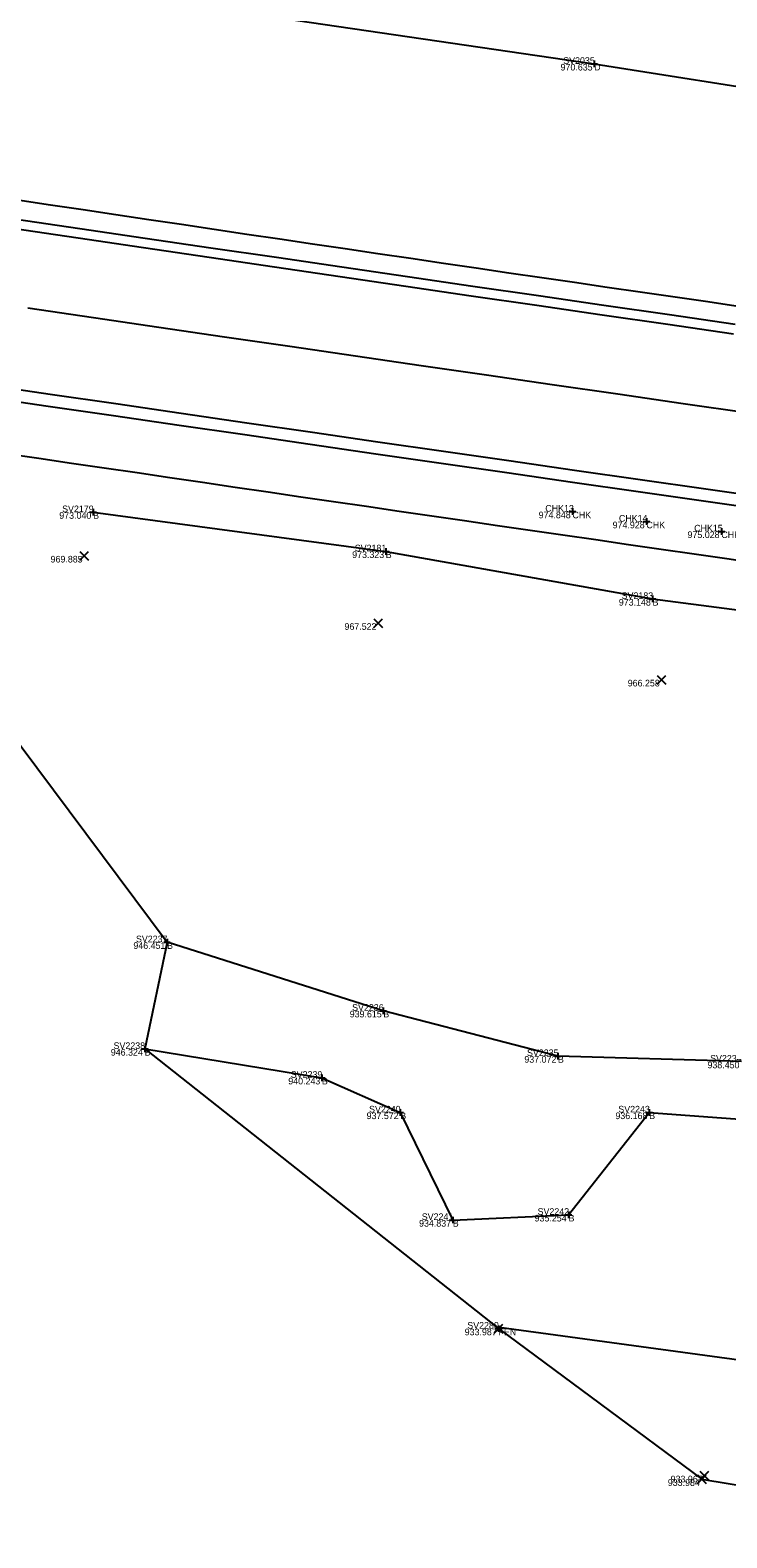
# Model space of a CAD drawing. Extents: x 2065431 to 2068157, y 709104 to 709719.
# Drawn here: x 2066286.8 to 2066392, y 709256 to 709483.7 of the extents above; entities that cross this region are included whole.
import ezdxf

# ---------------------------------------------------------------- set-up
doc = ezdxf.new("R2010")
doc.units = 0
for name, color, linetype in [('DT_X_Terrain_Boundary', 7, 'Continuous'), ('PM_X_Edge_Line', 7, 'Continuous'), ('PM_X_Lane_Line', 7, 'Continuous'), ('PV_X_EOP', 7, 'Continuous'), ('PV_X_Shoulder_Rumble_Strip', 7, 'Continuous'), ('RD_X_Fence', 7, 'Continuous'), ('RS_Raster1', 7, 'Continuous'), ('RW_X_CL_100_Bearings', 7, 'Continuous'), ('RW_X_Fee_WL', 7, 'Continuous'), ('SV_X_Break_Lines', 7, 'Continuous'), ('SV_X_Mon_Cells_Found', 7, 'Continuous'), ('SV_X_Text_Elevation', 7, 'Continuous'), ('SV_X_Text_Name', 7, 'Continuous')]:
    doc.layers.add(name, color=color, linetype=linetype)

msp = doc.modelspace()

# ---------------------------------------------------------------- linework, layer by layer
at = {"layer": 'DT_X_Terrain_Boundary'}
msp.add_lwpolyline([(2066248.51, 709424.93), (2066307.45, 709345.95), (2066304.08, 709329.83), (2066357.5, 709287.59), (2066388.19, 709264.84), (2066400.73, 709262.78), (2066407.99, 709258.2), (2066409.41, 709257.09), (2066415.2, 709255.99), (2066422, 709258.01), (2066442.41, 709259.57), (2066536.08, 709291.94), (2066609.07, 709301.93)], dxfattribs=at)
at = {"layer": 'PM_X_Edge_Line'}
for points in [[(2066284.13, 709453.83), (2066294.02, 709452.36), (2066303.92, 709450.89), (2066313.81, 709449.43), (2066323.7, 709447.97), (2066333.6, 709446.51), (2066343.49, 709445.06), (2066353.38, 709443.61), (2066363.28, 709442.17), (2066373.18, 709440.73), (2066383.07, 709439.29), (2066392.97, 709437.86)], [(2066279.93, 709430.2), (2066289.82, 709428.75), (2066299.71, 709427.3), (2066309.61, 709425.86), (2066319.51, 709424.42), (2066329.4, 709422.98), (2066339.3, 709421.55), (2066349.2, 709420.12), (2066359.09, 709418.69), (2066368.99, 709417.27), (2066378.89, 709415.85), (2066388.79, 709414.43), (2066398.69, 709413.01)]]:
    msp.add_lwpolyline(points, dxfattribs=at)
at = {"layer": 'PM_X_Lane_Line'}
msp.add_lwpolyline([(2066286.44, 709441.77), (2066296.34, 709440.31), (2066306.23, 709438.86), (2066316.12, 709437.4), (2066326.02, 709435.96), (2066335.91, 709434.51), (2066345.81, 709433.07), (2066355.71, 709431.63), (2066365.6, 709430.2), (2066375.5, 709428.76), (2066385.4, 709427.34), (2066395.29, 709425.91)], dxfattribs=at)
at = {"layer": 'PV_X_EOP'}
for points in [[(2066284.9, 709458.09), (2066289.84, 709457.35), (2066294.79, 709456.61), (2066299.73, 709455.87), (2066304.68, 709455.13), (2066309.62, 709454.39), (2066314.57, 709453.65), (2066319.52, 709452.92), (2066324.46, 709452.18), (2066329.41, 709451.45), (2066334.35, 709450.72), (2066339.3, 709449.99), (2066344.25, 709449.26), (2066349.19, 709448.53), (2066354.14, 709447.81), (2066359.09, 709447.08), (2066364.03, 709446.36), (2066368.98, 709445.64), (2066373.93, 709444.91), (2066378.88, 709444.2), (2066383.83, 709443.48), (2066388.77, 709442.76), (2066393.72, 709442.04)], [(2066283.13, 709419.79), (2066288.08, 709419.06), (2066293.02, 709418.33), (2066297.97, 709417.6), (2066302.92, 709416.88), (2066307.86, 709416.15), (2066312.81, 709415.42), (2066317.76, 709414.7), (2066322.7, 709413.97), (2066327.65, 709413.25), (2066332.6, 709412.52), (2066337.55, 709411.8), (2066342.49, 709411.08), (2066347.44, 709410.36), (2066352.39, 709409.64), (2066357.34, 709408.92), (2066362.28, 709408.2), (2066367.23, 709407.48), (2066372.18, 709406.76), (2066377.13, 709406.04), (2066382.08, 709405.33), (2066387.03, 709404.61), (2066391.97, 709403.9), (2066396.92, 709403.18)]]:
    msp.add_lwpolyline(points, dxfattribs=at)
at = {"layer": 'PV_X_Shoulder_Rumble_Strip'}
for points in [[(2066284.38, 709455.23), (2066294.28, 709453.77), (2066304.17, 709452.31), (2066314.06, 709450.86), (2066323.96, 709449.41), (2066333.85, 709447.96), (2066343.75, 709446.51), (2066353.64, 709445.07), (2066363.54, 709443.63), (2066373.43, 709442.19), (2066383.33, 709440.75), (2066393.23, 709439.31)], [(2066279.6, 709428.39), (2066289.5, 709426.94), (2066299.39, 709425.5), (2066309.29, 709424.06), (2066319.18, 709422.62), (2066329.08, 709421.18), (2066338.98, 709419.74), (2066348.87, 709418.31), (2066358.77, 709416.89), (2066368.67, 709415.46), (2066378.57, 709414.04), (2066388.47, 709412.62), (2066398.37, 709411.2)]]:
    msp.add_lwpolyline(points, dxfattribs=at)
at = {"layer": 'RD_X_Fence'}
msp.add_line((2066428.96, 709278), (2066357.61, 709287.76), dxfattribs=at)
at = {"layer": 'RS_Raster1'}
for p, q in [((2066371.45, 709478.62), (2066372.45, 709478.62)), ((2066371.95, 709479.12), (2066371.95, 709478.12)), ((2066371.95, 709478.62), (2066371.95, 709478.62)), ((2066296.29, 709411.41), (2066296.29, 709410.41)), ((2066368.67, 709411.49), (2066368.67, 709410.49)), ((2066295.79, 709410.91), (2066296.79, 709410.91)), ((2066296.29, 709410.91), (2066296.29, 709410.91)), ((2066368.17, 709410.99), (2066369.17, 709410.99)), ((2066368.67, 709410.99), (2066368.67, 709410.99)), ((2066379.34, 709409.48), (2066380.34, 709409.48)), ((2066379.84, 709409.98), (2066379.84, 709408.98)), ((2066379.84, 709409.48), (2066379.84, 709409.48)), ((2066390.66, 709408), (2066391.66, 709408)), ((2066391.16, 709408.5), (2066391.16, 709407.5)), ((2066391.16, 709408), (2066391.16, 709408)), ((2066339.98, 709404.99), (2066340.98, 709404.99)), ((2066340.48, 709405.49), (2066340.48, 709404.49)), ((2066340.48, 709404.99), (2066340.48, 709404.99)), ((2066380.27, 709397.8), (2066381.27, 709397.8)), ((2066380.77, 709398.3), (2066380.77, 709397.3)), ((2066380.77, 709397.8), (2066380.77, 709397.8)), ((2066306.95, 709345.95), (2066307.95, 709345.95)), ((2066307.45, 709346.45), (2066307.45, 709345.45)), ((2066307.45, 709345.95), (2066307.45, 709345.95)), ((2066339.61, 709335.6), (2066340.61, 709335.6)), ((2066340.11, 709336.1), (2066340.11, 709335.1)), ((2066340.11, 709335.6), (2066340.11, 709335.6)), ((2066303.58, 709329.83), (2066304.58, 709329.83)), ((2066304.08, 709330.33), (2066304.08, 709329.33)), ((2066304.08, 709329.83), (2066304.08, 709329.83)), ((2066365.98, 709328.76), (2066366.98, 709328.76)), ((2066366.48, 709329.26), (2066366.48, 709328.26)), ((2066366.48, 709328.76), (2066366.48, 709328.76)), ((2066330.33, 709325.48), (2066331.33, 709325.48)), ((2066330.83, 709325.98), (2066330.83, 709324.98)), ((2066330.83, 709325.48), (2066330.83, 709325.48)), ((2066342.17, 709320.24), (2066343.17, 709320.24)), ((2066342.67, 709320.74), (2066342.67, 709319.74)), ((2066342.67, 709320.24), (2066342.67, 709320.24)), ((2066379.76, 709320.24), (2066380.76, 709320.24)), ((2066380.26, 709320.74), (2066380.26, 709319.74)), ((2066380.26, 709320.24), (2066380.26, 709320.24)), ((2066350.6, 709304.5), (2066350.6, 709303.5)), ((2066367.58, 709304.78), (2066368.58, 709304.78)), ((2066368.08, 709305.28), (2066368.08, 709304.28)), ((2066368.08, 709304.78), (2066368.08, 709304.78)), ((2066350.1, 709304), (2066351.1, 709304)), ((2066350.6, 709304), (2066350.6, 709304)), ((2066357, 709287.59), (2066358, 709287.59)), ((2066357.5, 709288.09), (2066357.5, 709287.09)), ((2066357.5, 709287.59), (2066357.5, 709287.59))]:
    msp.add_line(p, q, dxfattribs=at)
at = {"layer": 'RW_X_CL_100_Bearings'}
for p, q in [((2066294.27, 709403.64), (2066295.61, 709404.97)), ((2066294.27, 709404.97), (2066295.61, 709403.64)), ((2066338.66, 709393.47), (2066339.99, 709394.8)), ((2066338.66, 709394.8), (2066339.99, 709393.47)), ((2066381.46, 709384.92), (2066382.79, 709386.26)), ((2066381.46, 709386.26), (2066382.79, 709384.92)), ((2066356.83, 709286.92), (2066358.17, 709288.25)), ((2066356.83, 709288.25), (2066358.17, 709286.92)), ((2066387.93, 709264.7), (2066389.26, 709266.04)), ((2066387.93, 709266.04), (2066389.26, 709264.7)), ((2066387.53, 709264.18), (2066388.86, 709265.51)), ((2066387.53, 709265.51), (2066388.86, 709264.18))]:
    msp.add_line(p, q, dxfattribs=at)
at = {"layer": 'RW_X_Fee_WL'}
msp.add_lwpolyline([(2066146.22, 709516.28), (2066201.46, 709507.43), (2066256.41, 709499.89), (2066309.66, 709487.73), (2066371.95, 709478.62), (2066434.46, 709468.76), (2066488.47, 709461.11), (2066543.09, 709454.02), (2066597.26, 709445.92), (2066653.85, 709437.6), (2066711.8, 709429.8), (2066769.12, 709422.19), (2066823.53, 709415.48), (2066878.43, 709408.48), (2066947.7, 709399.97)], dxfattribs=at)
at = {"layer": 'SV_X_Break_Lines'}
for points in [[(2066296.29, 709410.91), (2066340.48, 709404.99), (2066380.77, 709397.8), (2066419, 709392.82), (2066478.03, 709384.6), (2066527.44, 709376.82), (2066563.6, 709372.51), (2066611.9, 709361.92)], [(2066394.18, 709327.92), (2066366.48, 709328.76), (2066340.11, 709335.6), (2066307.45, 709345.95), (2066304.08, 709329.83), (2066330.83, 709325.48), (2066342.67, 709320.24), (2066350.6, 709304), (2066368.08, 709304.78), (2066380.26, 709320.24), (2066397.34, 709318.96)]]:
    msp.add_lwpolyline(points, dxfattribs=at)

# ---------------------------------------------------------------- texts
at = {"layer": 'SV_X_Mon_Cells_Found'}
for s, p in [('SV2035', (2066367.28, 709478.62)), ('SV2179', (2066291.61, 709410.91)), ('CHK13', (2066364.57, 709410.99)), ('CHK14', (2066375.69, 709409.48)), ('CHK15', (2066387.05, 709408)), ('SV2181', (2066335.8, 709404.99)), ('SV2183', (2066376.1, 709397.8)), ('SV2237', (2066302.76, 709345.95)), ('SV2236', (2066335.4, 709335.6)), ('SV2238', (2066299.38, 709329.83)), ('SV2235', (2066361.81, 709328.76)), ('SV2234', (2066389.46, 709327.92)), ('SV2239', (2066326.14, 709325.48)), ('SV2240', (2066337.96, 709320.24)), ('SV2243', (2066375.6, 709320.24)), ('SV2241', (2066345.92, 709304)), ('SV2242', (2066363.41, 709304.78)), ('SV2280', (2066352.79, 709287.59))]:
    msp.add_text(s, height=1, dxfattribs=at).set_placement(p)
at = {"layer": 'SV_X_Text_Elevation'}
for s, p in [('D', (2066371.95, 709477.62)), ('B', (2066296.29, 709409.91)), ('CHK', (2066368.67, 709409.99)), ('CHK', (2066379.84, 709408.48)), ('CHK', (2066391.16, 709407)), ('B', (2066340.48, 709403.99)), ('B', (2066380.77, 709396.8)), ('B', (2066307.45, 709344.95)), ('B', (2066340.11, 709334.6)), ('B', (2066304.08, 709328.83)), ('B', (2066366.48, 709327.76)), ('B', (2066330.83, 709324.48)), ('B', (2066342.67, 709319.24)), ('B', (2066380.26, 709319.24)), ('B', (2066368.08, 709303.78)), ('B', (2066350.6, 709303)), ('FEN', (2066357.5, 709286.59))]:
    msp.add_text(s, height=1, dxfattribs=at).set_placement(p)
at = {"layer": 'SV_X_Text_Name'}
for s, p in [('970.635', (2066366.88, 709477.62)), ('973.040', (2066291.18, 709409.91)), ('974.848', (2066363.57, 709409.99)), ('974.928', (2066374.74, 709408.48)), ('975.028', (2066386.05, 709407)), ('973.323', (2066335.41, 709403.99)), ('969.885', (2066289.87, 709403.31)), ('973.148', (2066375.67, 709396.8)), ('967.522', (2066334.25, 709393.14)), ('966.258', (2066377.02, 709384.59)), ('946.451', (2066302.37, 709344.95)), ('939.615', (2066335.04, 709334.6)), ('946.324', (2066298.96, 709328.83)), ('937.072', (2066361.41, 709327.76)), ('938.450', (2066389.06, 709326.92)), ('940.243', (2066325.76, 709324.48)), ('937.572', (2066337.59, 709319.24)), ('936.168', (2066375.16, 709319.24)), ('935.254', (2066362.96, 709303.78)), ('934.837', (2066345.51, 709303)), ('933.987', (2066352.4, 709286.59)), ('933.987', (2066352.4, 709286.59)), ('933.984', (2066383.07, 709263.84)), ('933.967', (2066383.5, 709264.37))]:
    msp.add_text(s, height=1, dxfattribs=at).set_placement(p)

doc.saveas('drawing.dxf')
